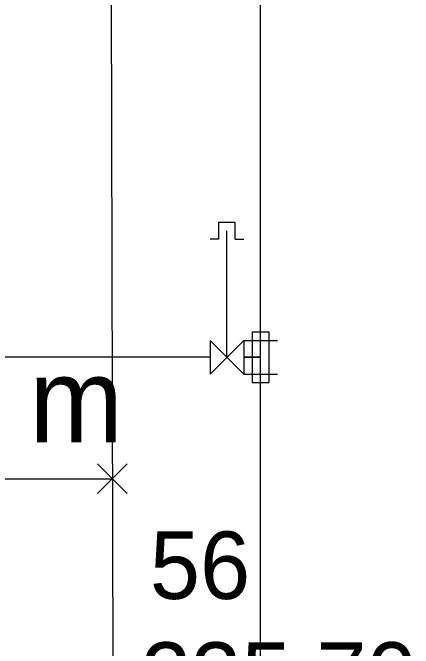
# Model space of a CAD drawing. Extents: x -264234 to -263604, y -1242346 to -1242049.
# Drawn here: x -263791.82 to -263785.88, y -1242205 to -1242195.57 of the extents above; entities that cross this region are included whole.
import ezdxf

# ---------------------------------------------------------------- set-up
doc = ezdxf.new("R2010")
doc.units = 0
for name, color, linetype in [('KFA_BODY_CISLO', 7, 'Continuous'), ('KFA_BODY_SYMBOL', 7, 'Continuous'), ('KFA_BODY_VYSKA', 7, 'Continuous'), ('KFA_DAZDOVA_KANALIZACIA_pripojky_tA_tC', 7, 'Continuous'), ('KFA_DAZDOVA_KANALIZACIA_pripojky_tA_tC_popis', 7, 'Continuous'), ('KFA_JESTV_IS_DSP_-_KANAL_DAZD', 7, 'Continuous'), ('KFA_SITUACIA_DSP', 7, 'Continuous')]:
    doc.layers.add(name, color=color, linetype=linetype)

msp = doc.modelspace()

# ---------------------------------------------------------------- linework, layer by layer
at = {"layer": 'KFA_BODY_SYMBOL'}
for p, q in [((-263790.561, -1242202.703), (-263790.119, -1242202.261)), ((-263790.119, -1242202.703), (-263790.561, -1242202.261))]:
    msp.add_line(p, q, dxfattribs=at)
at = {"layer": 'KFA_DAZDOVA_KANALIZACIA_pripojky_tA_tC'}
msp.add_line((-263795.2178, -1242202.4822), (-263790.3397, -1242202.4821), dxfattribs=at)
at = {"layer": 'KFA_JESTV_IS_DSP_-_KANAL_DAZD'}
msp.add_line((-263790.4278, -1242170.2731), (-263790.315, -1242211.5316), dxfattribs=at)
at = {"layer": 'KFA_SITUACIA_DSP'}
for p, q in [((-263788.1428, -1242250.1399), (-263788.1428, -1242082.6399)), ((-263788.7679, -1242198.6822), (-263788.7679, -1242198.9322)), ((-263788.5179, -1242198.6822), (-263788.7679, -1242198.6822)), ((-263788.5179, -1242198.9322), (-263788.5179, -1242198.6822)), ((-263788.6428, -1242200.6822), (-263788.6429, -1242198.8072)), ((-263788.7679, -1242198.9322), (-263788.8929, -1242198.9322)), ((-263788.5179, -1242198.9322), (-263788.3929, -1242198.9322)), ((-263788.2678, -1242200.3072), (-263788.2678, -1242201.0572)), ((-263788.0178, -1242200.3072), (-263788.2678, -1242200.3072)), ((-263788.0178, -1242201.0572), (-263788.0178, -1242200.3072)), ((-263788.8928, -1242200.4322), (-263788.8929, -1242200.9322)), ((-263788.8929, -1242200.9322), (-263788.3928, -1242200.4322)), ((-263788.3929, -1242200.9322), (-263788.8928, -1242200.4322)), ((-263788.3928, -1242200.4322), (-263788.3929, -1242200.9322)), ((-263788.3928, -1242200.4322), (-263787.8928, -1242200.4322)), ((-263788.8928, -1242200.6822), (-263800.5928, -1242200.6822)), ((-263788.1428, -1242200.6822), (-263788.3928, -1242200.6822)), ((-263788.3928, -1242200.6822), (-263788.1428, -1242200.6822)), ((-263788.3929, -1242200.9322), (-263787.8928, -1242200.9322)), ((-263788.2678, -1242201.0572), (-263788.0178, -1242201.0572)), ((-263795.2178, -1242202.4822), (-263790.3397, -1242202.4822))]:
    msp.add_line(p, q, dxfattribs=at)

# ---------------------------------------------------------------- texts
at = {"layer": 'KFA_BODY_CISLO'}
msp.add_text('56', height=1, dxfattribs=at).set_placement((-263789.7845, -1242204.2654))
at = {"layer": 'KFA_BODY_VYSKA'}
msp.add_text('235.70', height=1, dxfattribs=at).set_placement((-263789.9178, -1242205.9088))
at = {"layer": 'KFA_DAZDOVA_KANALIZACIA_pripojky_tA_tC_popis'}
msp.add_text('PDC3 - 4,88 m', height=1.25, dxfattribs=at).set_placement((-263801.2351, -1242201.9436))

doc.saveas('drawing.dxf')
